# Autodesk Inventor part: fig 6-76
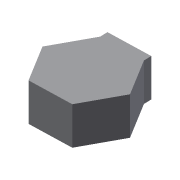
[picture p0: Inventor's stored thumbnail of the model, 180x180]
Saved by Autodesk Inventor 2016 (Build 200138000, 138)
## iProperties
Created: 2009-03
Part Number: fig 6-76
Document SubType Name: Modeling
Designer: Sham
Density: 1 g/cm^3
Material: Generic
Appearance: Default
Author: Sham
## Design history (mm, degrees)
sketch "Sketch5"
  geometry: L1 (-5.929, 9.627)-(5.372, 9.948); L2 (5.372, 9.948)-(11.301, 0.321); L3 (11.301, 0.321)-(5.929, -9.627); L4 (5.929, -9.627)-(-5.372, -9.948); L5 (-5.372, -9.948)-(-11.301, -0.321); L6 (-11.301, -0.321)-(-5.929, 9.627); 1 further point
  constraints: 12 end point, 13 other
extrude "Extrusion3" new body sketch "Sketch5" distance "d13" = 10; taper "d14" = 0 deg
thicken "Thicken2" dims "d15" = 2, "d16" = 2
body "Solid4"
